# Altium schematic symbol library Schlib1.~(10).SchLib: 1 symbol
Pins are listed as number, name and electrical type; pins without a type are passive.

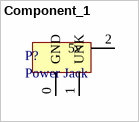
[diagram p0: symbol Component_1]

## Component_1
designator P?, comment Power Jack
footprint PCBComponent_1
pins: 0 GND (power), 1 UNK (power), 2 5v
